// Mitsubishi GX Works2 project: PLC Q12H CONNECT V-BOX   PLC: Q12H

PROGRAM MAIN
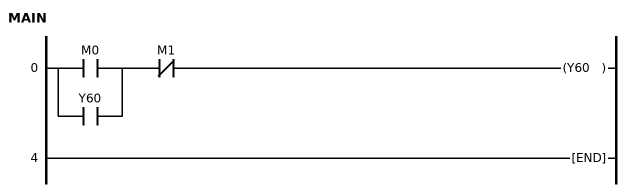
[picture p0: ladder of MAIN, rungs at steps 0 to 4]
0     LD      M0
      OR      Y60
      ANI     M1
      OUT     Y60
4     END
END_PROGRAM
